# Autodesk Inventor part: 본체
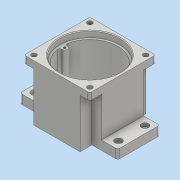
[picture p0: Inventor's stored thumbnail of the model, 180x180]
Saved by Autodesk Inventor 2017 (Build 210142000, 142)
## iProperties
Part Number: 본체
Material: 일반
Document SubType Name: Modeling
Designer: user
Density: 1 g/cm^3
Appearance: 기본값
Mass: 324.565 g
Surface Area: 793.683 cm^2
Volume: 324.565 cm^3
Author: user
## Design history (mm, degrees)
sketch "스케치1"
  geometry: L1 (0, 30)-(140, 30); L2 (140, 30)-(140, -30); L3 (140, -30)-(0, -30); L4 (0, -30)-(0, 30); L5 (37, 47)-(103, 47); L6 (103, 47)-(103, -47); L7 (103, -47)-(37, -47); L8 (37, -47)-(37, 47); 6 further points
  constraints: 16 end point, 5 midpoint, 4 parallel, 2 coincident, 2 horizontal, 2 horizontal alignment, 2 perpendicular, 1 vertical alignment
  dimensions: "d0" = 140 distance between parallel lines of L2 L4; "d1" = 60 distance between parallel lines of L3 L1; "d2" = 66 distance between parallel lines of L8 L6; "d3" = 94 distance between parallel lines of L7 L5
extrude "돌출1" new body sketch "스케치1" distance "d4" = 13; taper "d5" = 0 deg
sketch "스케치2"
  geometry: L1 (37, 47)-(103, 47); L2 (103, 47)-(103, -47); L3 (103, -47)-(37, -47); L4 (37, -47)-(37, 47); L5 (103, 47)-(37, 47) reference; L6 (103, 30)-(103, 47) reference; L7 (23, 30)-(117, 30); L8 (117, 30)-(117, -30); L9 (117, -30)-(23, -30); L10 (23, -30)-(23, 30); L11 (140, 30)-(103, 30) reference; L12 (103, -30)-(140, -30) reference; 1 further point
  constraints: 16 end point, 4 collinear, 4 parallel, 2 horizontal, 2 perpendicular
  dimensions: "d6" = 66 distance between parallel lines of L2 L4; "d7" = 94 distance between parallel lines of L3 L1; "d8" = 94 distance of L7.start L7.end; "d10" = 14 distance between parallel lines of L4 L10
extrude "돌출2" join sketch "스케치2" distance "d11" = 57; taper "d12" = 0 deg
sketch "스케치3"
  geometry: L1 (23, 47)-(117, 47); L2 (117, 47)-(117, -47); L3 (117, -47)-(23, -47); L4 (23, -47)-(23, 47); L5 (103, 47)-(37, 47) reference; L6 (117, -30)-(117, 30) reference; L7 (37, -47)-(103, -47) reference; L8 (23, 30)-(23, -30) reference; 1 further point
  constraints: 8 end point, 4 collinear, 2 parallel, 1 horizontal, 1 perpendicular
extrude "돌출3" join sketch "스케치3" distance "d13" = 10; taper "d14" = 0 deg
sketch "스케치4"
  geometry: C1 r 43 at (70, 0); 1 further point
  constraints: 1 centre point, 1 horizontal alignment
  dimensions: "d15" = 70 distance of C1.centre point (0, 0); "d16" = 86 diameter of C1
extrude "돌출4" cut sketch "스케치4" distance "d17" = 9; taper "d18" = 0 deg
sketch "스케치5"
  geometry: L1 (-70, 30)-(-70, -30) reference; C1 r 40 at (0, 0); 2 further points
  constraints: 1 centre point, 1 horizontal alignment, 1 midpoint
  dimensions: "d19" = 80 diameter of C1; "d20" = 70 distance of point (-70, 0) C1.centre
extrude "돌출5" cut sketch "스케치5" distance "d21" = 62; taper "d22" = 0 deg
sketch "스케치11"
  geometry: L1 (0, 0)-(-140, 0); L2 (-117, 47)-(-23, 47) reference; L3 (-70, 47)-(-70, 0); L4 (-70, 0)-(-70, 11); L5 (0, -30)-(0, 30) reference; C1 r 27.5 at (-70, 11)
  constraints: 6 end point, 2 midpoint, 1 centre point, 1 coincident, 1 horizontal, 1 point on line
  dimensions: "d33" = 11 distance of L3.end L4.end; "d34" = 55 diameter of C1; "d35" = 70 distance from line of L4.end L5
extrude "돌출8" join sketch "스케치11" distance "d36" = 7; taper "d37" = 0 deg
sketch "스케치12"
  geometry: L1 (70, -41)-(70, 19) reference; C1 r 16 at (0, 0); C2 r 27.5 at (0, 0) reference; 1 further point
  constraints: 1 centre point, 1 concentric
  dimensions: "d38" = 32 diameter of C1
extrude "돌출9" cut sketch "스케치12" distance "d40" = 8.3; taper "d41" = 0 deg
sketch "스케치13"
  geometry: L1 (70, -41)-(70, 19) reference; C1 r 12.5 at (0, 0); C2 r 16 at (0, 0) reference; 1 further point
  constraints: 1 centre point, 1 concentric
  dimensions: "d44" = 25 diameter of C1
extrude "돌출10" cut sketch "스케치13" distance "d45" = 4.7; taper "d46" = 0 deg
sketch "스케치16"
  geometry: C1 r 17.5 at (0, 0); C2 r 16 at (0, 0) reference; 1 further point
  constraints: 1 centre point, 1 concentric
  dimensions: "d47" = 35 diameter of C1
extrude "돌출11" cut sketch "스케치16" distance "d48" = 10; taper "d49" = 0 deg
sketch "스케치19"
  geometry: C1 r 21 at (0, 11); C2 r 15 at (0, -20); C3 r 12.5 at (0, 11) reference; 1 further point
  constraints: 2 centre point, 1 coincident, 1 vertical alignment
  dimensions: "d53" = 42 diameter of C1; "d54" = 30 diameter of C2; "d55" = 31 distance of C2.centre C1.centre
extrude "돌출12" join sketch "스케치19" distance "d56" = 7; taper "d57" = 0 deg
hole "구멍1" diameter "d60" = 35; stored, may be unused: countersink angle "d64" = 90 deg, drill point angle "d66" = 0 deg; dims "d61" = 6, "d62" = 4, "d63" = 2, "d65" = 10, "d67" = 10, "d68" = 10
sketch "스케치23"
  geometry: L1 (47, 47)-(-47, 47) reference; L2 (70, -30)-(70, 30) reference; C1 r 11 at (0, -20); A1 r 15 centre (0, -20) between (-8.978, -7.984) and (8.978, -7.984) reference; 1 further point
  constraints: 1 centre point, 1 concentric
  dimensions: "d72" = 22 diameter of C1
extrude "돌출13" cut sketch "스케치23" distance "d73" = 7; taper "d74" = 0 deg
sketch "스케치24"
  geometry: C1 r 9.5 at (0, 0); C2 r 11 at (0, 0) reference; 1 further point
  constraints: 1 centre point, 1 concentric
  dimensions: "d75" = 19 diameter of C1
extrude "돌출14" cut sketch "스케치24" distance "d76" = 3; taper "d77" = 0 deg
fillet "모깎기1" dims "d78" = 3
sketch "스케치25"
  geometry: L1 (0, 30)-(-37, 30) reference; L2 (-37, -30)-(0, -30) reference; L3 (0, -30)-(0, 30) reference; L4 (-103, 30)-(-140, 30) reference; L5 (-140, -30)-(-103, -30) reference; C1 r 2.25 at (-10, 19); C2 r 2.25 at (-10, -19); C3 r 2.25 at (-130, 19); C4 r 2.25 at (-130, -19); 1 further point
  constraints: 4 centre point
  dimensions: "d79" = 4.5 diameter of C1; "d81" = 4.5 diameter of C2; "d82" = 38 distance of C2.centre C1.centre; "d83" = 11 distance from line of C1.centre L1; "d84" = 11 distance from line of C2.centre L2; "d85" = 4.5 diameter of C3; "d86" = 4.5 diameter of C4; "d87" = 38 distance of C4.centre C3.centre; "d88" = 120 distance of C1.centre C3.centre; "d89" = 10 distance from line of L3 C1.centre; "d90" = 11 distance from line of L4 C3.centre; "d91" = 11 distance from line of L5 C4.centre
extrude "돌출15" cut sketch "스케치25" distance "d92" = 8; taper "d93" = 0 deg
sketch "스케치26"
  geometry: L1 (10, 11)-(10, -49) reference; L2 (-13, 11)-(10, 11) reference; C1 r 5 at (0, 0); 1 further point
  constraints: 1 centre point
  dimensions: "d94" = 10 diameter of C1; "d95" = 10 distance from line of L1 C1.centre; "d96" = 11 distance from line of C1.centre L2
extrude "돌출16" cut sketch "스케치26" distance "d97" = 5; taper "d98" = 0 deg
sketch "스케치28"
  geometry: L1 (-23, 30)-(-23, 47) reference; L2 (-117, 47)-(-117, 30) reference; L3 (-23, 47)-(-37, 47) reference; C1 r 3.5 at (-30, 40); C2 r 3.5 at (-110, 40); 1 further point
  constraints: 2 centre point
  dimensions: "d105" = 80 distance of C2.centre C1.centre; "d106" = 7 distance from line of C1.centre L1; "d107" = 7 distance from line of L2 C2.centre; "d108" = 7 diameter of C2; "d109" = 7 diameter of C1; "d111" = 40 vertical distance of point (0, 0) C1.centre
extrude "돌출17" cut sketch "스케치28" stored distance "d112" = 100; taper "d113" = 0 deg
sketch "스케치29"
  geometry: L1 (35.778, 3.994)-(39.8, 3.994); L2 (35.778, -3.994)-(39.8, -3.994); L3 (-39.8, 3.994)-(-35.778, 3.994); L4 (-35.778, -3.994)-(-39.8, -3.994); A1 r 36 centre (0, 0) between (-36, 0) and (36, 0); A2 r 4 centre (-36, 0) between (-35.778, 3.994) and (-35.778, -3.994); A3 r 4 centre (36, 0) between (35.778, 3.994) and (35.778, -3.994); A4 r 40 centre (0, 0) between (39.8, 3.994) and (39.8, -3.994) reference; 1 further point
  constraints: 13 point on circle, 8 end point, 3 centre point, 3 horizontal, 1 parallel
  dimensions: "d114" = 72 diameter of A1; "d115" = 8 diameter of A2; "d116" = 8 diameter of A3
extrude "돌출18" join sketch "스케치29" distance "d117" = 62; taper "d118" = 0 deg
sketch "스케치30"
  geometry: C1 r 2 at (-36, 0); C2 r 2 at (36, 0); A1 r 4 centre (-36, 0) between (-35.778, -3.994) and (-35.778, 3.994) reference; A2 r 4 centre (36, 0) between (35.778, 3.994) and (35.778, -3.994) reference; 1 further point
  constraints: 2 centre point, 2 coincident
  dimensions: "d119" = 4 diameter of C1; "d120" = 4 diameter of C2
hole "구멍2" sketch "스케치30" at (36, 0), (-36, 0) diameter "d121" = 3.242; stored, may be unused: countersink angle "d125" = 90 deg, drill point angle "d127" = 118 deg; dims "d122" = 7, "d123" = 4, "d124" = 2, "d126" = 9
chamfer "모따기1" distance "d128" = 1; stored, may be unused: second distance "d129" = 2, angle "d130" = 45 deg
node "작업 평면1"
chamfer "모따기2" distance "d131" = 1; stored, may be unused: second distance "d132" = 2, angle "d133" = 45 deg
chamfer "모따기3" distance "d134" = 0.8; stored, may be unused: second distance "d135" = 2, angle "d136" = 30 deg
fillet "모깎기2" dims "d137" = 3
fillet "모깎기3" dims "d138" = 3
sketch "스케치32"
  geometry: L1 (0, 0)-(0, -70) reference; L2 (80, -80)-(-14, -80) reference; 2 further points
  constraints: 1 other
  dimensions: "d140" = 33 distance from line of L1 point (33, -40); "d144" = 40 distance from line of point (33, -40) L2
feature "엠보싱1" sketch "스케치32" dims "d142" = 0.5, "d143" = 0
fillet "모깎기5" dims "d145" = 3
fillet "모깎기6" dims "d146" = 3
node "솔리드1"
pattern_linear "직사각형 패턴1" dims "d101" = 38, "d104" = 120
mirror "미러1"
